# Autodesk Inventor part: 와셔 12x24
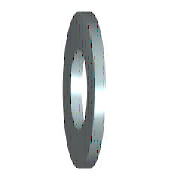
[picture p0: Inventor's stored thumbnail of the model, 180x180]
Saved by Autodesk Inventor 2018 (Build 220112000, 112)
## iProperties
IsCustomPart: 1
Created: 2012-02
Part Number: 와셔 12x24
Material: 스테인리스강
Description: 평면 와셔
Document SubType Name: Modeling
Standard: KS B 1326
Designer: mduedu
Standards Organization: KS
Language: ko-KR
Size Designation: 12x24
Categories: <MemberInstance><Categories><Category DisplayName="조임쇠" InternalName="e4da775c-781d-43d5-af7c-5136215cf5a6" Mnemonic="FSTN"><Category DisplayName="와셔" InternalN
Density: 1 g/cm^3
Appearance: 파란색 - 벽 페인트 - 광택
Author: mduedu
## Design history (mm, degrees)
sketch "스케치"
  geometry: C1 r 12 at (0, 0); C2 r 6.5 at (0, 0); 1 further point
  constraints: 2 centre point, 2 coincident
  dimensions: "d0" = 13 diameter of C2 (= SD1); "d1" = 24 diameter of C1 (= SD2)
extrude "본체" new body sketch "스케치" distance "d2" = 2.5 (= SD); taper "d3" = 0 deg
workaxis "Work Axis1"
workplane "Work Plane1"
body "Solid1"
other parameters: "SD1" = 13 [user parameter; used in 1 equation term], "SD2" = 24 [user parameter; used in 1 equation term], "SD" = 2.5 [user parameter; used in 1 equation term], "d4" = 0, "d5" = 0, "d6" = 0, "d7" = 0, "NND" = 12 [user parameter]
